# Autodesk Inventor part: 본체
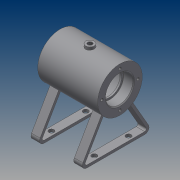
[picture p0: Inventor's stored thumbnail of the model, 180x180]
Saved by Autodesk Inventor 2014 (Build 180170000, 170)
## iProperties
Created: 2016-03
Part Number: 본체
Material: 일반
Document SubType Name: Modeling
Designer: SEC
Density: 1 g/cm^3
Appearance: 기본값
Author: SEC
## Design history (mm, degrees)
sketch "스케치1"
  geometry: L1 (-35, 0)-(35, 0); L2 (-35, -16)-(-35, -26); L3 (-35, -26)-(35, -26); L4 (35, -26)-(35, -16); L5 (35, -16)-(23, -16); L6 (23, -16)-(23, -14); L7 (23, -14)-(21, -14); L8 (21, -14)-(21, -21); L9 (21, -21)-(-21, -21); L10 (-21, -21)-(-21, -14); L11 (-21, -14)-(-23, -14); L12 (-23, -14)-(-23, -16); L13 (-23, -16)-(-35, -16); 3 further points
  constraints: 26 end point, 10 parallel, 3 collinear, 3 vertical alignment, 2 midpoint, 2 perpendicular, 1 coincident, 1 horizontal
  dimensions: "d0" = 70 distance of L1.start L1.end; "d1" = 52 diameter of L3 L1; "d2" = 32 diameter of L13 L1; "d3" = 28 diameter of L11 L1; "d4" = 42 diameter of L9 L1; "d5" = 12 distance of L12.end L2.start; "d6" = 42 distance of L8.end L9.end
revolve "회전1" sketch "스케치1" stored, may be unused: angle "d7" = 90 deg
sketch "스케치2"
  geometry: 2 further points
  constraints: 1 vertical alignment
  dimensions: "d8" = 21 distance of point (0, 0) point (0, 21)
hole "구멍1" sketch "스케치2" at (0, 21) diameter "d9" = 3.242; stored, may be unused: countersink angle "d13" = 90 deg, drill point angle "d15" = 118 deg; dims "d10" = 8, "d11" = 4, "d12" = 2, "d14" = 10
fillet "모깎기1" dims "d19" = 0.3
chamfer "모따기1" distance "d20" = 1; stored, may be unused: second distance "d21" = 2, angle "d22" = 45 deg
node "작업 평면1"
sketch "스케치3"
  geometry: L1 (-16.613, -20)-(-38.264, -57.5); L2 (-33.934, -65)-(33.934, -65); L3 (38.264, -57.5)-(16.613, -20); L4 (0, 26)-(0, -26); L5 (14.183, -21.791)-(35.666, -59); L6 (33.934, -62)-(-33.934, -62); L7 (-35.666, -59)-(-14.183, -21.791); A1 r 26 centre (0, 0) between (-16.613, -20) and (16.613, -20) reference; A2 r 5 centre (-33.934, -60) between (-38.264, -57.5) and (-33.934, -65); A3 r 5 centre (33.934, -60) between (33.934, -65) and (38.264, -57.5); A4 r 2 centre (33.934, -60) between (33.934, -62) and (35.666, -59); A5 r 2 centre (-33.934, -60) between (-35.666, -59) and (-33.934, -62); 3 further points
  constraints: 14 end point, 14 point on circle, 4 centre point, 4 tangent, 2 midpoint, 1 coincident, 1 equal radius, 1 horizontal, 1 perpendicular, 1 vertical alignment, 2 other
  dimensions: "d24" = 30 deg angle of L1 L4; "d25" = 30 deg angle of L4 L3; "d26" = 45 distance from line of L2 L1.start; "d27" = 65 distance from line of L2 point (0, 0); "d28" = 5 radius of A2; "d29" = 3 distance between parallel lines of L2 L6; "d30" = 3 distance between parallel lines of L1 L7; "d31" = 3 distance between parallel lines of L3 L5
extrude "돌출1" join sketch "스케치3" distance "d32" = 10; taper "d33" = 0 deg
sketch "스케치4"
  geometry: L1 (-10, 0)-(-10, 67.868) reference; 3 further points
  constraints: 1 vertical alignment
  dimensions: "d34" = 20 vertical distance of point (-5, 53.934) point (20, 33.934); "d35" = 40 distance of point (-5, 13.934) point (-5, 53.934); "d36" = 5 distance from line of L1 point (-5, 53.934)
hole "구멍2" sketch "스케치4" at (-5, 53.934), (-5, 13.934) diameter "d37" = 6; stored, may be unused: countersink angle "d41" = 90 deg, drill point angle "d43" = 118 deg; dims "d38" = 8, "d39" = 4, "d40" = 2, "d42" = 10
node "작업 평면2"
sketch "스케치5"
  geometry: C1 r 5 at (0, 0); 1 further point
  constraints: 1 centre point, 1 coincident
  dimensions: "d45" = 10 diameter of C1
extrude "돌출2" join sketch "스케치5" stored distance "d46" = 10 (= d45); taper "d47" = 0 deg
sketch "스케치6"
  geometry: 2 further points
  constraints: 1 coincident
hole "구멍3" sketch "스케치6" at (0, 0) diameter "d48" = 5.188; stored, may be unused: countersink angle "d52" = 90 deg, drill point angle "d54" = 118 deg; dims "d49" = 8, "d50" = 4, "d51" = 2, "d53" = 10
node "솔리드1"
pattern_circular "원형 패턴1" dims angle "d17" = 360 deg
mirror "대칭1"
mirror "대칭2"
other parameters: "d44" = 29
